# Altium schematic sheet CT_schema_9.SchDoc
size 391 x 238 mm
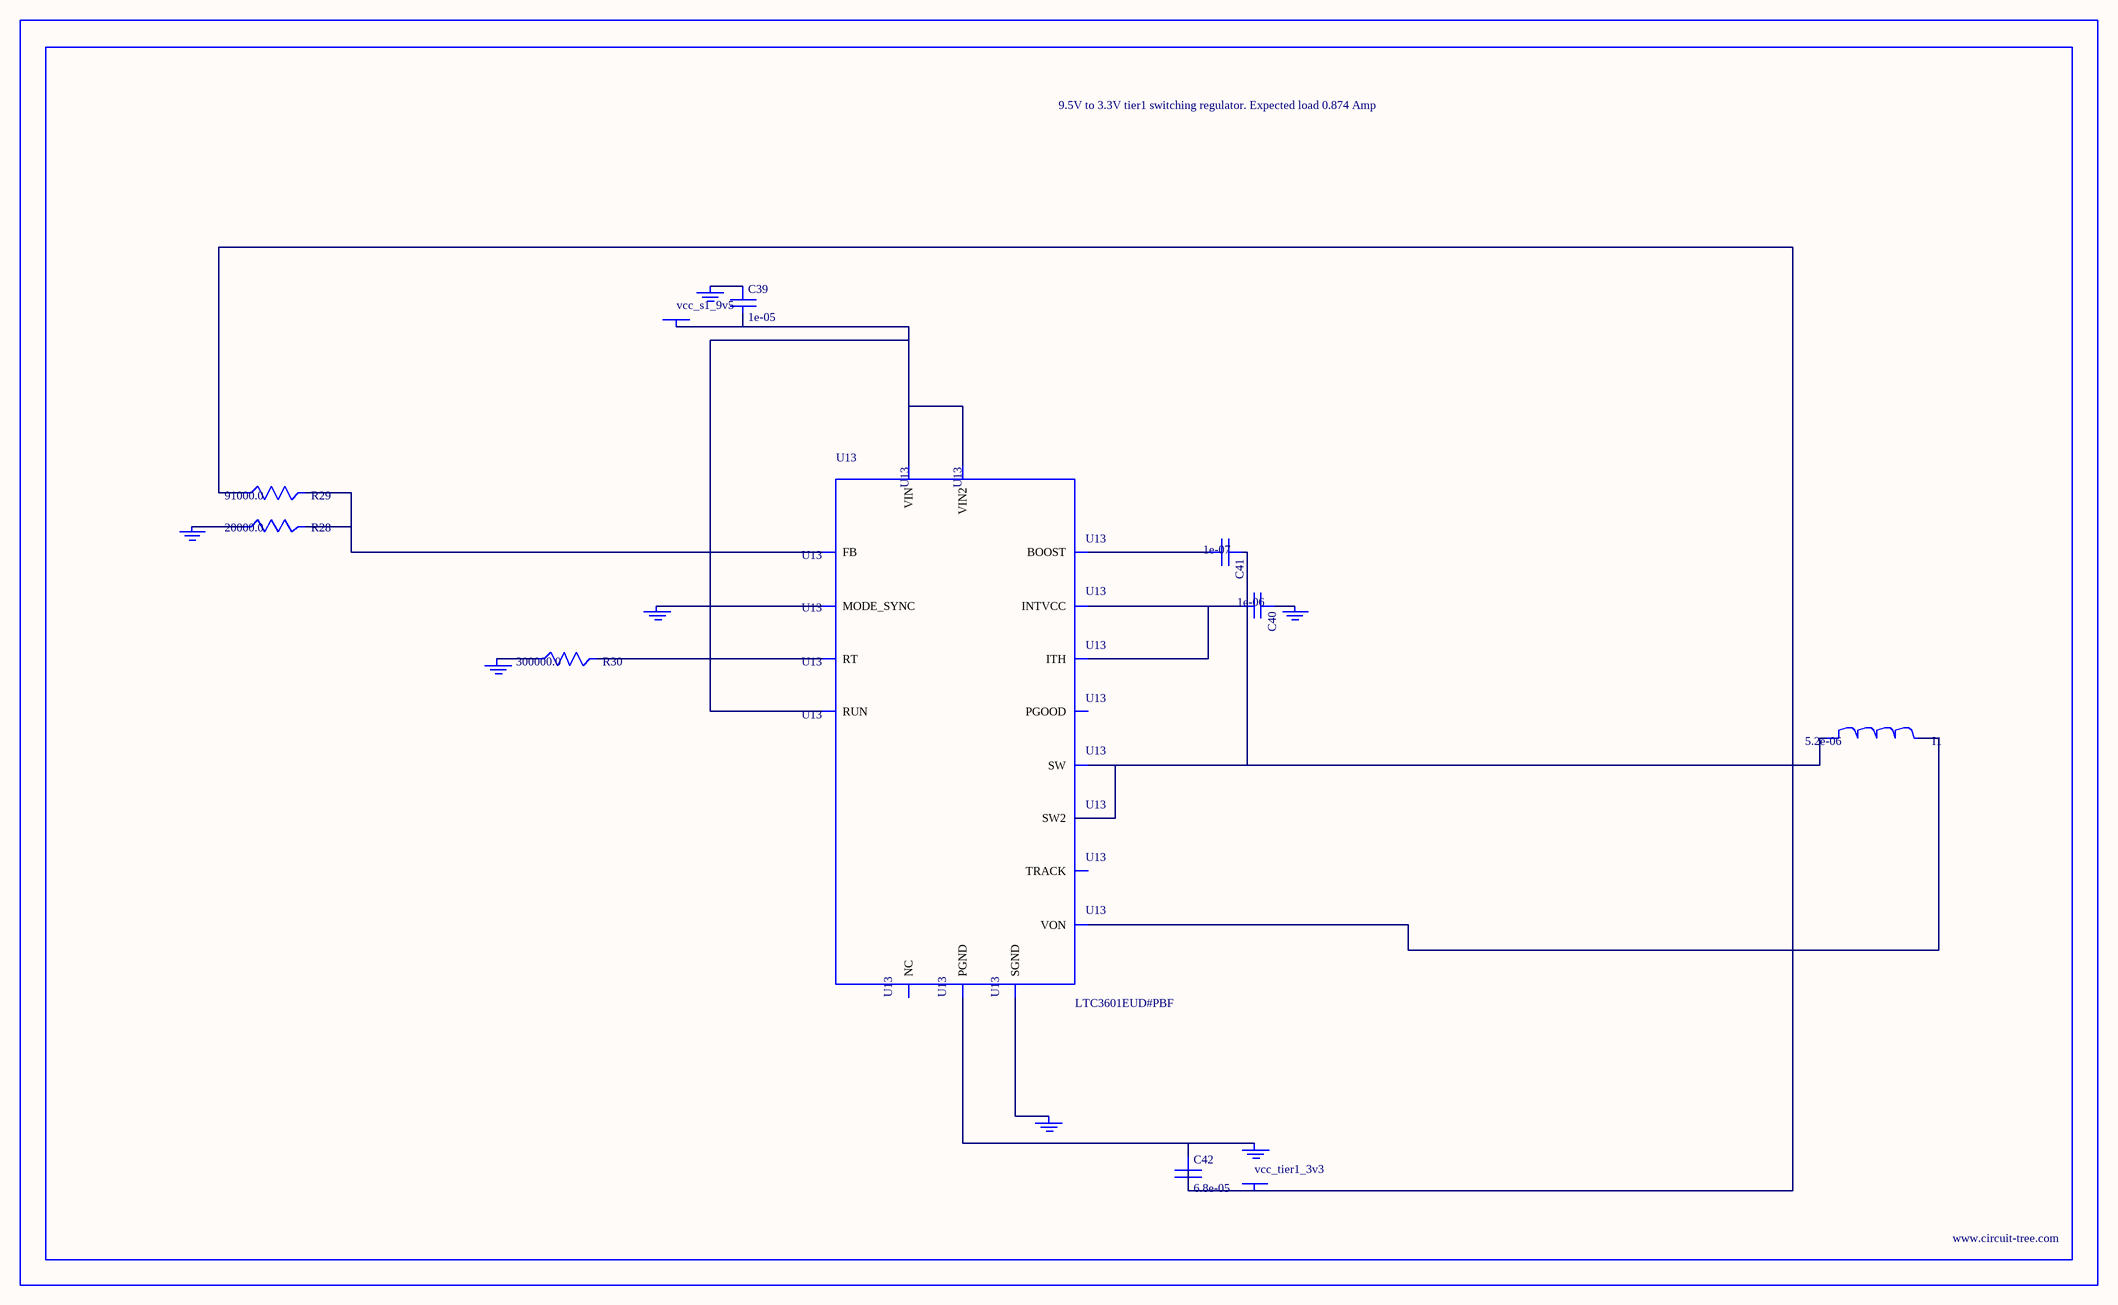
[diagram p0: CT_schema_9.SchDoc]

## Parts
BORDER8  (no value)
C39  1e-05  [C0805]
C40  1e-06  [C0603]
C41  1e-07  [C0402]
C42  6.8e-05  [2220]
GND_INSTANCE_8_0  (no value)
GND_INSTANCE_8_1  (no value)
GND_INSTANCE_8_2  (no value)
GND_INSTANCE_8_3  (no value)
GND_INSTANCE_8_4  (no value)
GND_INSTANCE_8_5  (no value)
GND_INSTANCE_8_6  (no value)
I1  5.2e-06  [DR1040]
POWER_INSTANCE_8_0  vcc_s1_9v5
POWER_INSTANCE_8_1  vcc_tier1_3v3
R28  20000.0  [R0603]
R29  91000.0  [R0603]
R30  300000.0  [R0603]
U13  LTC3601EUD#PBF  [QFN-16_EP]

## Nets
NetC39_1: C39.1 GND_INSTANCE_8_5.0(GND)
NetC39_2: C39.2 POWER_INSTANCE_8_0.0(PWR) U13.14(RUN) U13.15(VIN) U13.16(VIN2)
NetC40_1: C40.1 GND_INSTANCE_8_1.0(GND)
NetC40_2: C40.2 U13.7(INTVCC) U13.12(ITH)
NetC41_1: C41.1 I1.1 U13.3(SW) U13.4(SW2)
NetC41_2: C41.2 U13.6(BOOST)
NetC42_1: C42.1 GND_INSTANCE_8_6.0(GND) U13.17(PGND)
NetC42_2: C42.2 I1.2 POWER_INSTANCE_8_1.0(PWR) R29.1 U13.8(VON)
NetGND_INSTANCE_8_0_0: GND_INSTANCE_8_0.0(GND) U13.1(MODE_SYNC)
NetGND_INSTANCE_8_2_0: GND_INSTANCE_8_2.0(GND) U13.9(SGND)
NetGND_INSTANCE_8_3_0: GND_INSTANCE_8_3.0(GND) R30.1
NetGND_INSTANCE_8_4_0: GND_INSTANCE_8_4.0(GND) R28.1
NetR28_2: R28.2 R29.2 U13.11(FB)
NetR30_2: R30.2 U13.10(RT)

Not connected (* = marked no-connect by the designer): U13 2(PGOOD) 5(NC) 13(TRACK)

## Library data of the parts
BORDER8 = BORDER_PAGE8
C39 = C0805C106K8RACTU
C40 = C0603C105K3RACTU
C41 = C0402C104K3RACTU
C42 = C5750X5R1A686M
GND_INSTANCE_8_0-GND_INSTANCE_8_6 = GND
I1 = DR1040-5R2-R
POWER_INSTANCE_8_0 POWER_INSTANCE_8_1 = PWR
R28 = RC0603JR-0720KL
R29 = RC0603JR-0791KL
R30 = RC0603JR-07300KL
